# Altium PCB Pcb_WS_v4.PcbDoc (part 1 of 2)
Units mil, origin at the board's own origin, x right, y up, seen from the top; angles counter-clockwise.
Board outline 3890 x 3890 mil, 2 copper layers (Top Layer, Bottom Layer), stack 50.044 mil thick; 84 components, 65 nets, 260 pads, 445 vias.
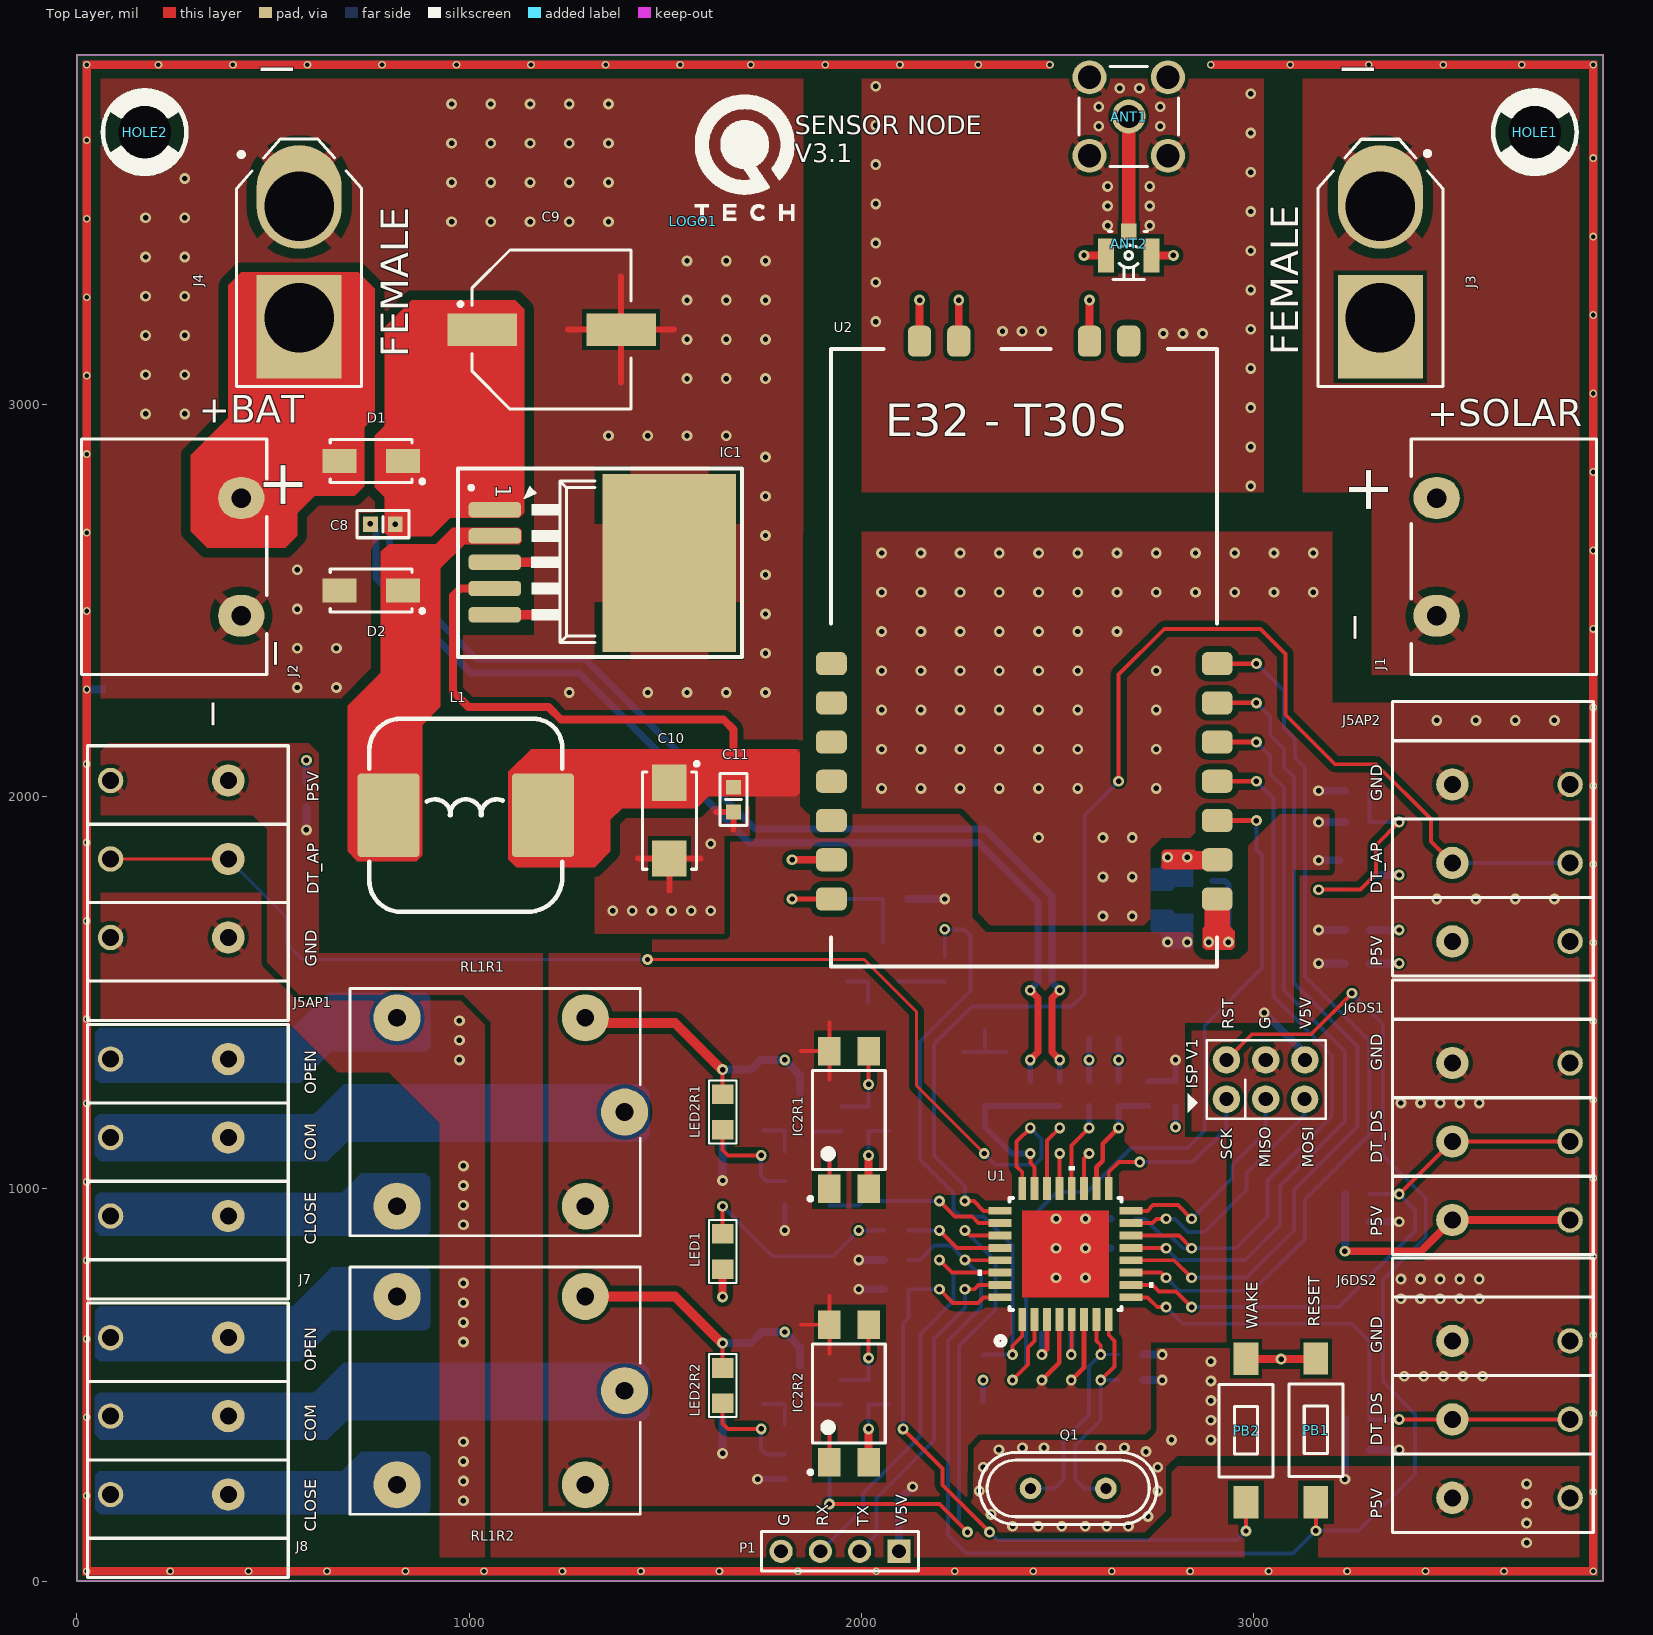
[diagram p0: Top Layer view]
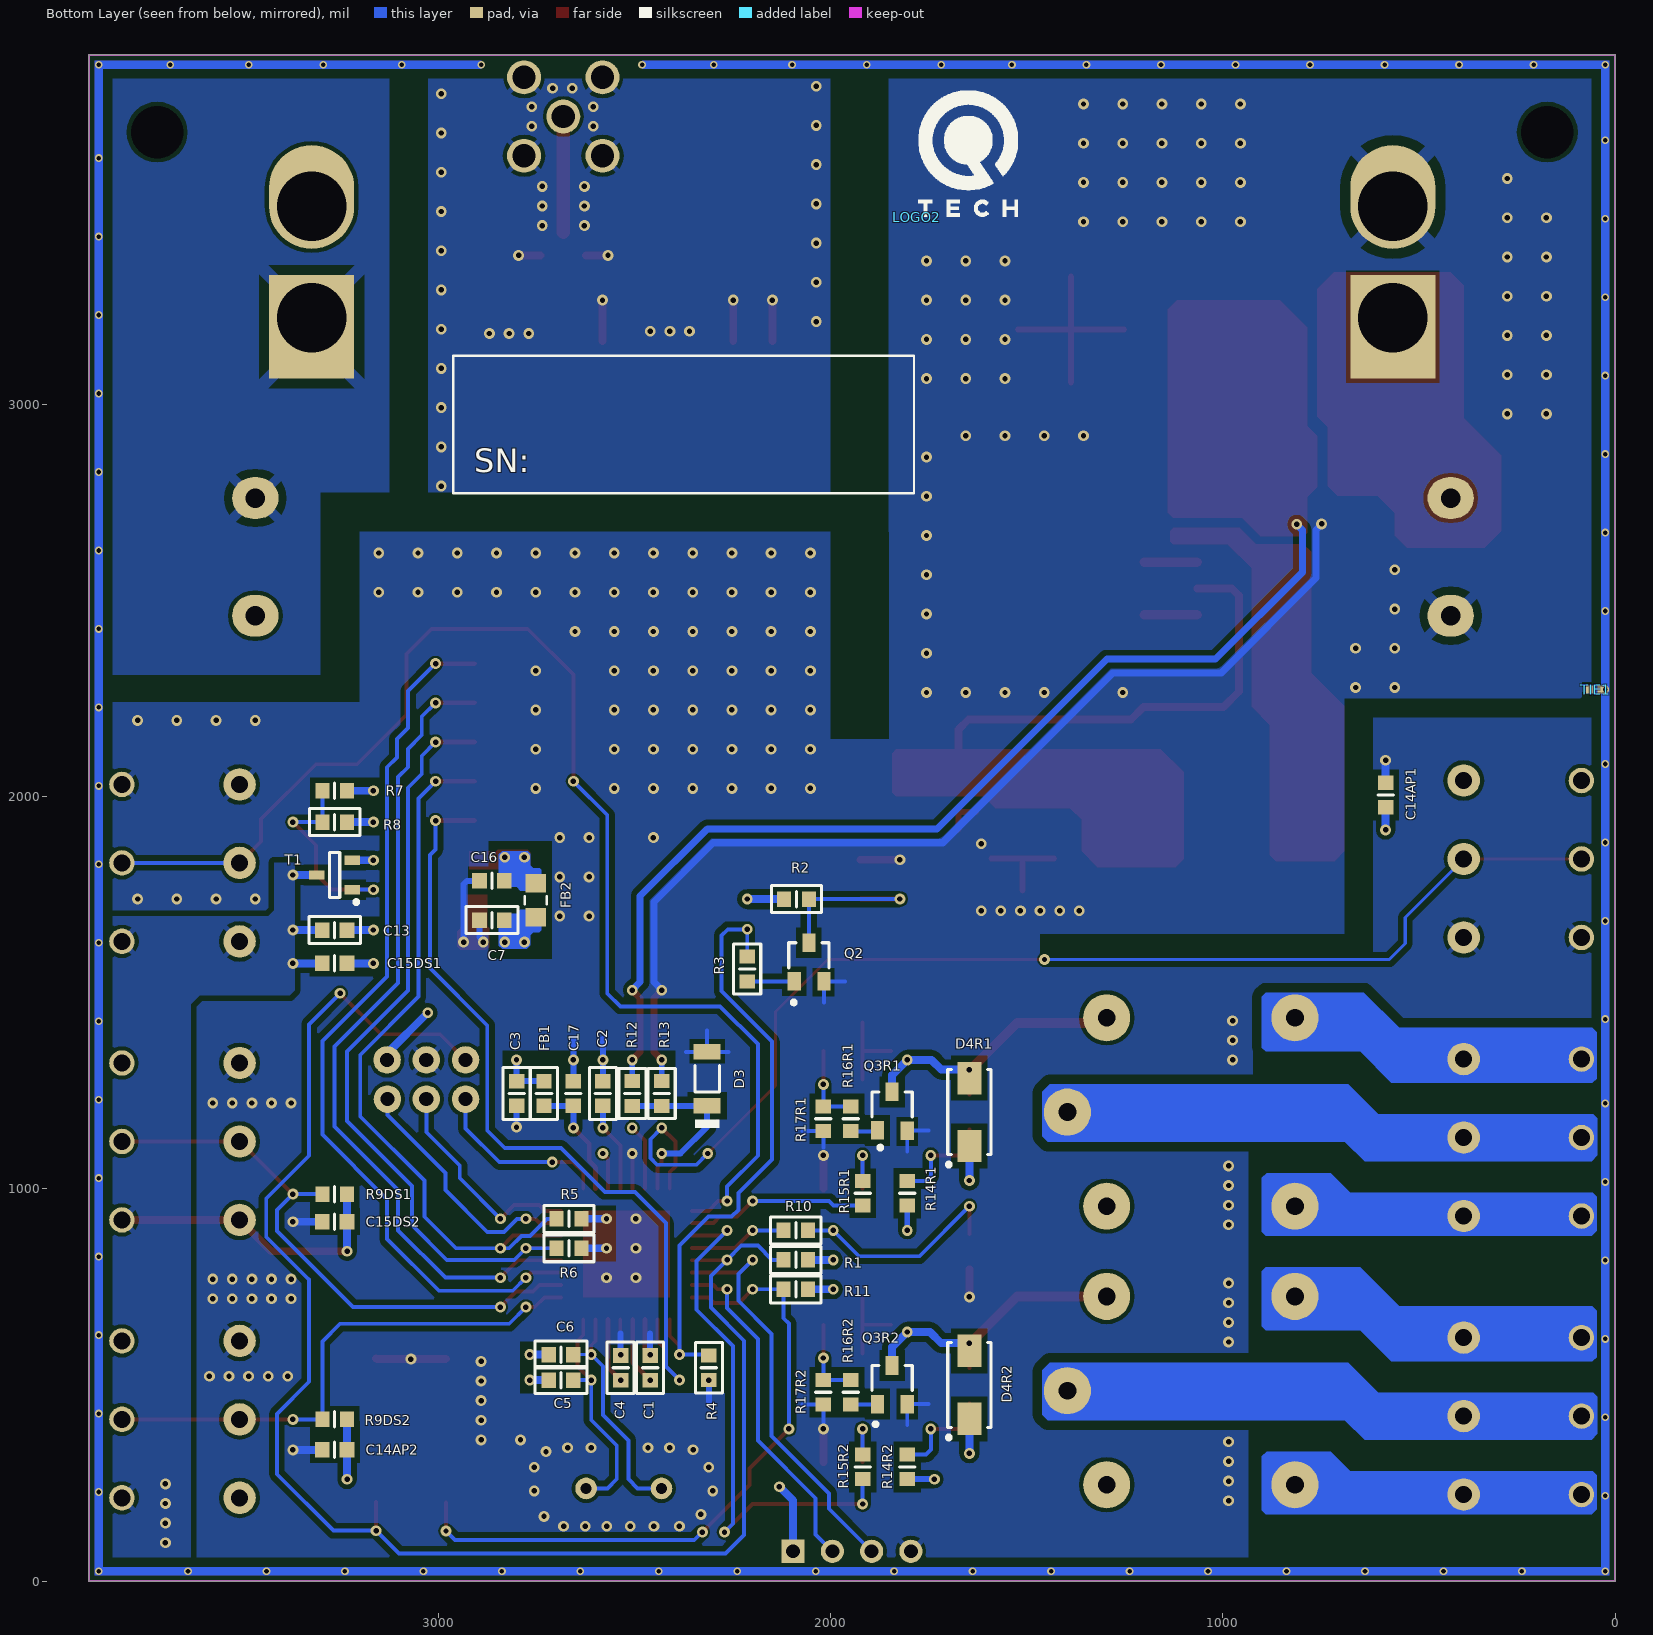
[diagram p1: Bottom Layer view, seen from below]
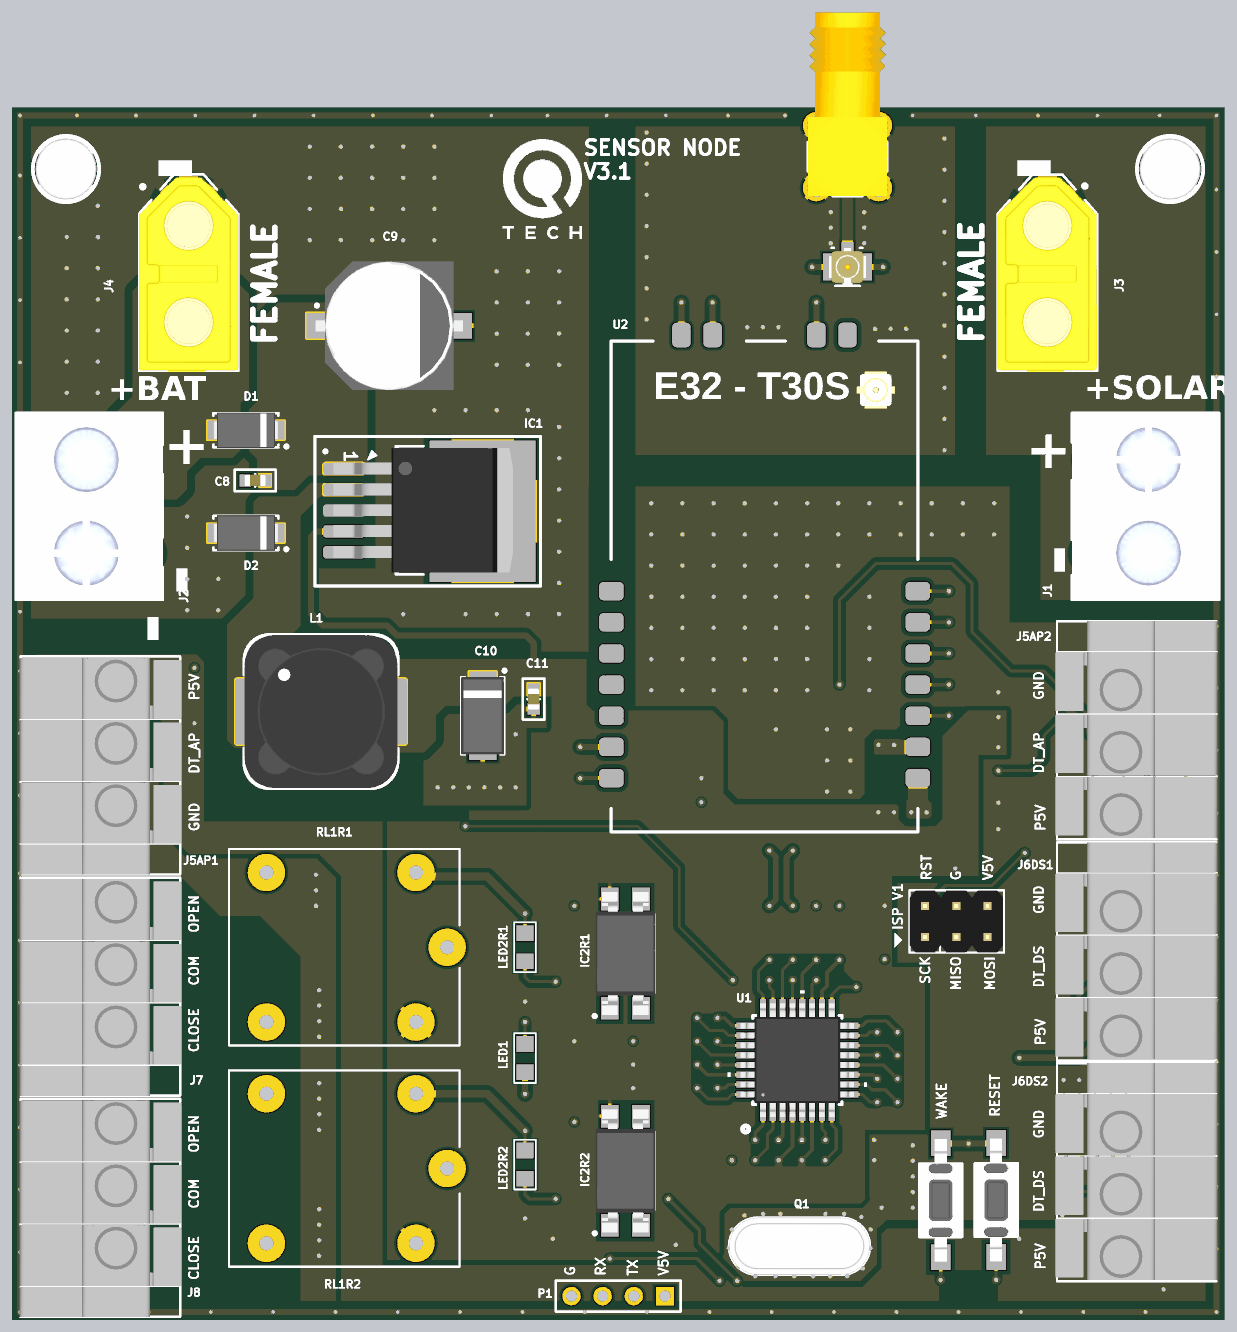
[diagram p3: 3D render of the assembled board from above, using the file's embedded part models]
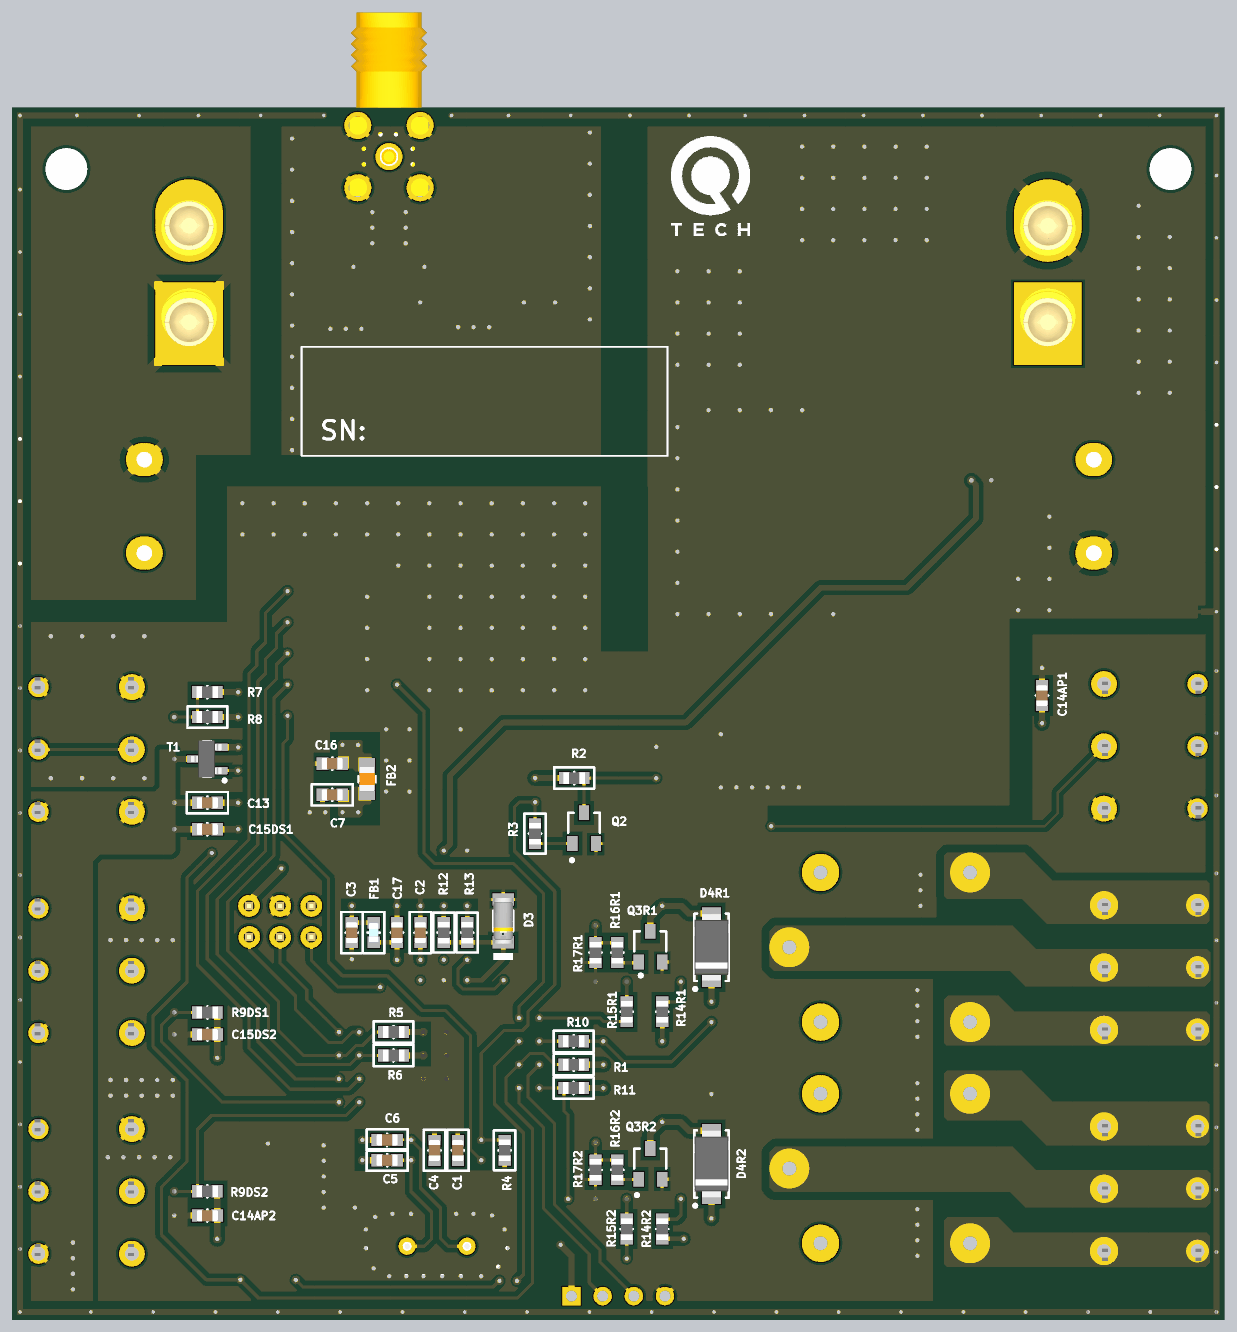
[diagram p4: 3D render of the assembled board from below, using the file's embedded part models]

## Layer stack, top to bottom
Top Solder: solder mask 0.4, Solder Resist, Dk 3.5
Top Layer: signal copper 1.4
Dielectric 1: dielectric 47.2441, FR-4, Dk 4.8
Bottom Layer: signal copper 1.4
Bottom Solder: solder mask 0.4, Solder Resist, Dk 3.5

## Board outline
0,0 0,3890 3890,3890 3890,0

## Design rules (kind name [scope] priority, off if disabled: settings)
Clearance ANT [InNet('ANT_M1') vs InNet('GND_ANT')] p1: gap=7.87 ignorepadtopadclearanceinfootprint=FALSE
Clearance Keep_Out [OnLayer('Keep-Out Layer')] p2: gap=5 ignorepadtopadclearanceinfootprint=FALSE
Clearance [All] p3: gap=10 ignorepadtopadclearanceinfootprint=FALSE except(5: Via-Poly Via-Region; 15: Track-Poly Track-Region SMDPad-Poly SMDPad-Region Poly-Poly; 25: Poly-Region)
ComponentClearance KF-conn_Clearance [InComponentClass('KF_conn') vs InComponentClass('KF_conn')] p1: gap=5 collisioncheckmode=3 verticalgap=0 showdistances=FALSE
ComponentClearance HS_Comp_Clearance [InComponentClass('HS_Comp') vs IsComponent] p2: gap=165 collisioncheckmode=3 verticalgap=0 showdistances=FALSE
ComponentClearance IC_Comp_Clearance [InComponentClass('IC_Comp') vs IsComponent] p3: gap=150 collisioncheckmode=3 verticalgap=0 showdistances=FALSE
ComponentClearance conn-th_Clearance [InComponentClass('conn-th') vs IsComponent and not InComponentClass('conn-th')] p4: gap=150 collisioncheckmode=3 verticalgap=0 showdistances=FALSE
ComponentClearance chip-ge_Clearance [InComponentClass('chip-ge') vs InAnyComponent] p5: gap=75 collisioncheckmode=3 verticalgap=0 showdistances=FALSE
ComponentClearance chip-0603_Clearance [InComponentClass('chip-0603') vs IsComponent] p6: gap=25 collisioncheckmode=3 verticalgap=0 showdistances=FALSE
HoleSize [All] p1: absolutevalues=TRUE maxlimit=100 minlimit=11.81 maxpercent=80.000 minpercent=20.000
HoleToHoleClearance [All] p1: gap=20 allowstackedmicrovias=TRUE
MinimumSolderMaskSliver MinimumForIC [HasFootprint('32A_ATM-M') vs HasFootprint('32A_ATM-M')] p1: minsoldermaskwidth=3
MinimumSolderMaskSliver [All] p2: minsoldermaskwidth=5
NetAntennae [All] p1 off: netantennaetolerance=0
PolygonConnect [All] p1: thpad.connectstyle=Relief thpad.reliefconductorwidth=13.78 thpad.reliefentries=4 thpad.polygonreliefangle="45 Angle" thpad.airgapwidth=10 smdpad.connectstyle=NoConnect smdpad.reliefconductorwidth=11.81 smdpad.reliefentries=4 smdpad.polygonreliefangle="45 Angle" smdpad.airgapwidth=10 via.connectstyle=Direct via.reliefconductorwidth=10 via.reliefentries=4 via.polygonreliefangle="90 Angle" via.airgapwidth=10
RoomDefinition Top_Level [InComponentClass('Top_Level')] p1: confinementstyle=ConfineIn formatcopy=TRUE lockcomponents=FALSE outline -1409.14,-1234.46 590.86,-1234.46 590.86,-234.46 -1409.14,-234.46
RoomDefinition R2 [InComponentClass('R2')] p2: confinementstyle=ConfineIn formatcopy=TRUE lockcomponents=FALSE outline -1409.14,-1234.46 590.86,-1234.46 590.86,-234.46 -1409.14,-234.46
RoomDefinition R1 [InComponentClass('R1')] p3: confinementstyle=ConfineIn formatcopy=TRUE lockcomponents=FALSE outline -1409.14,-1234.46 590.86,-1234.46 590.86,-234.46 -1409.14,-234.46
RoomDefinition PWR [InComponentClass('PWR')] p4: confinementstyle=ConfineIn formatcopy=TRUE lockcomponents=FALSE outline -1409.14,-1234.46 590.86,-1234.46 590.86,-234.46 -1409.14,-234.46
RoomDefinition Main [InComponentClass('Main')] p5: confinementstyle=ConfineIn formatcopy=TRUE lockcomponents=FALSE outline -1409.14,-1234.46 590.86,-1234.46 590.86,-234.46 -1409.14,-234.46
RoomDefinition Lora [InComponentClass('Lora')] p6: confinementstyle=ConfineIn formatcopy=TRUE lockcomponents=FALSE outline -1409.14,-1234.46 590.86,-1234.46 590.86,-234.46 -1409.14,-234.46
RoomDefinition Hardware [InComponentClass('Hardware')] p7: confinementstyle=ConfineIn formatcopy=TRUE lockcomponents=FALSE outline -1409.14,-1234.46 590.86,-1234.46 590.86,-234.46 -1409.14,-234.46
RoomDefinition DS2 [InComponentClass('DS2')] p8: confinementstyle=ConfineIn formatcopy=TRUE lockcomponents=FALSE outline -1409.14,-1234.46 590.86,-1234.46 590.86,-234.46 -1409.14,-234.46
RoomDefinition DS1 [InComponentClass('DS1')] p9: confinementstyle=ConfineIn formatcopy=TRUE lockcomponents=FALSE outline -1409.14,-1234.46 590.86,-1234.46 590.86,-234.46 -1409.14,-234.46
RoomDefinition AP2 [InComponentClass('AP2')] p10: confinementstyle=ConfineIn formatcopy=TRUE lockcomponents=FALSE outline -1409.14,-1234.46 590.86,-1234.46 590.86,-234.46 -1409.14,-234.46
RoomDefinition AP1 [InComponentClass('AP1')] p11: confinementstyle=ConfineIn formatcopy=TRUE lockcomponents=FALSE outline -1409.14,-1234.46 590.86,-1234.46 590.86,-234.46 -1409.14,-234.46
RoutingVias [All] p1: holewidth=13.78 width=27.56 viastyle="Through Hole" minholewidth=11.81 minwidth=23.62 maxholewidth=19.68 maxwidth=39.37
SilkToSilkClearance [All] p1: silktosilkclearance=3
SilkToSolderMaskClearance [IsPad] p1: minsilkscreentomaskgap=5 clearancetoexposedcopper=TRUE
SolderMaskExpansion [All] p1: expansion=4 istentingtop=FALSE
Width [All] p1: maxlimit=196.85 minlimit=8 preferedwidth=10
23 further rules are at their usual default settings.

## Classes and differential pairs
component class Hardware: HOLE1 HOLE2 LOGO1 LOGO2
channel class Sensor_DS18b20_1Wire: DS1 DS2
channel class Sensor_AirPressure_1Wire: AP1 AP2
channel class Relay: R1 R2
component class Top_Level: D3 J7 J8 LED1 P1 PB2 R10 R11 R12 R13 TIE1
component class R2: D4R2 IC2R2 LED2R2 Q3R2 R14R2 R15R2 R16R2 R17R2 RL1R2
component class R1: D4R1 IC2R1 LED2R1 Q3R1 R14R1 R15R1 R16R1 R17R1 RL1R1
component class Main: C1 C2 C3 C4 C5 C6 C17 FB1 "ISP V1" PB1 Q1 R1 U1
component class Lora: ANT1 ANT2 C7 C16 FB2 Q2 R2 R3 R4 R5 R6 U2
component class DS2: C15DS2 J6DS2 R9DS2
component class DS1: C15DS1 J6DS1 R9DS1
component class AP2: C14AP2 J5AP2
component class AP1: C14AP1 J5AP1
component class PWR: C8 C9 C10 C11 C13 D1 D2 IC1 J1 J2 J3 J4 L1 R7 R8 T1

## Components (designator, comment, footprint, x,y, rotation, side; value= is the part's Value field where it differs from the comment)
ANT1 "Coax_1Female_1Shield" "HUBER-SUHNER_85 SMA-50-0-101/111 NE" 2680.84,3733 r90 top
ANT2 "U.FL" HIROSE_U.FL-R-SMT-1(10) 2680.84,3379 r180 top
C1 "100nF" CAPC1608X87N 2459.61,543.68 r90 bottom
C2 "100nF" CAPC1608X87N 2580,1242.82 r270 bottom
C3 "100nF" CAPC1608X87N 2800,1242.82 r270 bottom
C4 "100nF" CAPC1608X87N 2534.61,543.68 r90 bottom
C5 "100nF" CAPC1608X87N 2686.8,512.18 r0 bottom value=22pF
C6 "100nF" CAPC1608X87N 2686.8,577.18 r0 bottom value=22pF
C7 "100nF" CAPC1608X87N 2862.78,1684.95 r180 bottom
C8 "100nF" CAPC1608X87N 780,2693.89 r180 top
C9 "470uF" CAPAE1030X1020N 1210,3190 r0 top
C10 "100uF" CAPMP6032X280N 1510,1938.49 r270 top
C11 "100nF" CAPC1608X87N 1673.55,1992 r270 top
C13 "100nF" CAPC1608X87N 3263.5,1659.46 r180 bottom
C14AP1 "100nF" CAPC1608X87N 585,2003.5 r270 bottom (schematic designator C14)
C14AP2 "100nF" CAPC1608X87N 3263.5,334.46 r180 bottom (schematic designator C14)
C15DS1 "100nF" CAPC1608X87N 3263.5,1574.46 r0 bottom (schematic designator C15)
C15DS2 "100nF" CAPC1608X87N 3263.5,915.77 r180 bottom (schematic designator C15)
C16 "2.2uF" CAPC1608X87N 2862.78,1784.92 r180 bottom
C17 "2.2uF" CAPC1608X87N 2655,1242.82 r270 bottom
D1 "SS16" DIOM5127X229N 750,2855 r180 top
D2 "SS16" DIOM5127X229N 750,2525 r180 top
D3 "BZV55-B5V1" DIOMELF3515N 2314.07,1280.22 r90 bottom
D4R1 "BZG03C220" DIOM5326X230N 1645.86,1195.54 r90 bottom (schematic designator D4)
D4R2 "BZG03C220" DIOM5326X230N 1645.86,500 r90 bottom (schematic designator D4)
FB1 "Ferrite bead Case 0603" Chip_0603 2730,1242.82 r90 bottom
FB2 "Ferrite bead Case 0805" CHIP_0805 2751.03,1735.52 r90 bottom
HOLE1 "HOLE" "HOLE M3" 3716.02,3693.14 r0 top
HOLE2 "HOLE" "HOLE M3" 172.71,3693.14 r0 top
IC1 "LM2596" TO263-5 1065.04,2730.82 r270 top
IC2R1 "SFH6156-4" SOIC254P977X406-4N 1967.86,1175.54 r90 top (schematic designator IC2)
IC2R2 "SFH6156-4" SOIC254P977X406-4N 1967.86,478.26 r90 top (schematic designator IC2)
"ISP V1" "Connector 3x2" JP3x2 3030,1278.39 r0 top
J1 "CON KF7.62-2P" "CON KF7.62-2P" 3465.86,2610.54 r270 top locked
J2 "CON KF7.62-2P" "CON KF7.62-2P" 418.93,2610.54 r90 top locked
J3 "XT60-FM" XT60-FM 3322.31,3362.43 r270 top locked
J4 "XT60-FM" XT60-FM 566.41,3362.43 r270 top locked
J5AP1 "KF142V-3P" "CON KF142V-3P-5.08" 85.86,2040.54 r270 top (schematic designator J5)
J5AP2 "KF142V-3P" "CON KF142V-3P-5.08" 3805.86,1630.54 r90 top (schematic designator J5)
J6DS1 "KF142V-3P" "CON KF142V-3P-5.08" 3805.86,920.54 r90 top (schematic designator J6)
J6DS2 "KF142V-3P" "CON KF142V-3P-5.08" 3805.86,212.26 r90 top (schematic designator J6)
J7 "KF142V-3P" "CON KF142V-3P-5.08" 85.86,1330.54 r270 top
J8 "KF142V-3P" "CON KF142V-3P-5.08" 85.86,620.54 r270 top
L1 "33uH" L_SMD 794.25,1952 r90 top
LED1 "LED" L-0805 1645.86,840 r270 top value="LED 3 ly Single Colour"
LED2R1 "LED" L-0805 1645.86,1195.54 r90 top value="LED 3 ly Single Colour" (schematic designator LED2)
LED2R2 "LED" L-0805 1645.86,498.26 r90 top value="LED 3 ly Single Colour" (schematic designator LED2)
LOGO1 "LOGO" LOGO-QTECH 1570.5,3466.4 r0 top
LOGO2 "LOGO" LOGO-QTECH 1780,3476 r180 bottom
P1 "Header 4" HDR1X4 2095,76 r180 top
PB1 "Push Button" PB_TYCO_FSMSM 3157.89,384.26 r90 top
PB2 "Push Button" PB_TYCO_FSMSM 2979.87,383.49 r90 top
Q1 "20MHz" XTAL_HC-49/U 2526.55,236.12 r0 top
Q2 "C1815" SOT23-3 2055.2,1577.8 r180 bottom
Q3R1 "C1815" SOT23-3 1842.86,1197.59 r180 bottom (schematic designator Q3)
Q3R2 "C1815" SOT23-3 1842.86,500.31 r180 bottom (schematic designator Q3)
R1 "10k" RESC1608X55N 2088.21,818.79 r0 bottom
R2 "10k" RESC1608X55N 2086.5,1738.49 r0 bottom value=4k7
R3 "10k" RESC1608X55N 2212.06,1560.29 r270 bottom value=1k
R4 "10k" RESC1608X55N 2309.61,543.68 r90 bottom value=1k
R5 "4k7" RESC1608X55N 2666.17,923.39 r180 bottom value=10k
R6 "4k7" RESC1608X55N 2666.17,848.39 r180 bottom value=10k
R7 "1k" RESC1608X55N 3263.5,2014.46 r0 bottom
R8 "10k" RESC1608X55N 3263.5,1934.46 r0 bottom
R9DS1 "4k7" RESC1608X55N 3263.5,986.31 r180 bottom (schematic designator R9)
R9DS2 "4k7" RESC1608X55N 3263.5,412.26 r180 bottom (schematic designator R9)
R10 "10k" RESC1608X55N 2088.21,893.79 r180 bottom value=200
R11 "10k" RESC1608X55N 2088.21,743.79 r0 bottom
R12 "10k" RESC1608X55N 2505,1242.82 r270 bottom value=2M
R13 "10k" RESC1608X55N 2430,1242.82 r90 bottom value=1M
R14R1 "1k" RESC1608X55N 1804.06,988.52 r90 bottom value=200 (schematic designator R14)
R14R2 "1k" RESC1608X55N 1804.06,291.24 r90 bottom value=200 (schematic designator R14)
R15R1 "1k" RESC1608X55N 1917.86,988.52 r90 bottom (schematic designator R15)
R15R2 "1k" RESC1608X55N 1917.86,291.24 r90 bottom (schematic designator R15)
R16R1 "1k" RESC1608X55N 1947.86,1178.52 r270 bottom value=200 (schematic designator R16)
R16R2 "1k" RESC1608X55N 1947.86,481.24 r270 bottom value=200 (schematic designator R16)
R17R1 "10k" RESC1608X55N 2017.86,1178.52 r90 bottom (schematic designator R17)
R17R2 "10k" RESC1608X55N 2017.86,481.24 r90 bottom (schematic designator R17)
RL1R1 "Relay 10A/12V" RL_SPDT_10A 1395.86,1195.54 r180 top value="Relay SPDT, 10A, 12V" (schematic designator RL1)
RL1R2 "Relay 10A/12V" RL_SPDT_10A 1395.86,485.54 r180 top value="Relay SPDT, 10A, 12V" (schematic designator RL1)
T1 "BSH203" SOT95P230X110-3N 3263.5,1799.74 r0 bottom
TIE1 "TIE" tie 49.76,2272.5 r0 bottom
U1 "ATmega328-AU" 32A_ATM-M 2519.8,833.59 r90 top
U2 "E32-T30S" E32-T30S 2906.43,3140.85 r180 top locked

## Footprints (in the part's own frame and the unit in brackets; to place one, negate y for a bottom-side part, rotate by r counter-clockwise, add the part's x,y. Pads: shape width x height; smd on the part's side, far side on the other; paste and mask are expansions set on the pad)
32A_ATM-M [mil]
  rect 58x20 smd: 1(-167,110.24) 2(-167,78.74) 3(-167,47.24) 4(-167,15.75) 5(-167,-15.75) 6(-167,-47.24) 7(-167,-78.74) 8(-167,-110.24) 17(167,-110.24) 18(167,-78.74) 19(167,-47.24) 20(167,-15.75) 21(167,15.75) 22(167,47.24) 23(167,78.74) 24(167,110.24)
  rect 20x58 smd: 9(-110.24,-167) 10(-78.74,-167) 11(-47.24,-167) 12(-15.75,-167) 13(15.75,-167) 14(47.24,-167) 15(78.74,-167) 16(110.24,-167) 25(110.24,167) 26(78.74,167) 27(47.24,167) 28(15.75,167) 29(-15.75,167) 30(-47.24,167) 31(-78.74,167) 32(-110.24,167)
  silkscreen extent -231,-224 224,224, body extent -182,-182 182,182, height 47
CAPAE1030X1020N [mm] "Capacitor, Aluminium Electrolytric, 10.3mm L X 10.3mm W X 10.2mm H, IPC Medium Density"
  rect 4.5x2.1 smd: 1(-4.5,0) 2(4.5,0)
  silkscreen extent -6.02,-5.15 5.15,5.15, body extent -6,-5.25 6,5.25, height 10.2
CAPC1608X87N [mm] "Chip Capacitor, Body 1.6x0.8mm IPC Medium Density"
  rect 0.95x1 smd: 1(-0.8,0) 2(0.8,0)
  silkscreen extent -1.68,-0.87 1.68,0.87, body extent -0.87,-0.47 0.88,0.48, height 0.87
CAPMP6032X280N [mm] "Capacitor, Polarized, Molded  Body 6.0x3.2mm, IPC Medium Density"
  rect 2.35x2.25 smd: 1(-2.45,0) 2(2.45,0)
  silkscreen extent -3.8,-1.75 3.15,1.9, body extent -3.15,-1.75 3.15,1.75, height 2.8
Chip_0603 [mm]
  rect 0.95x1 smd: 1(0.8,0) 2(-0.8,0)
  silkscreen extent -1.68,-0.87 1.68,0.87, body extent -0.8,-0.4 0.8,0.4, height 0.95
CHIP_0805 [mm]
  rect 1.2x1.3 smd mask+0.064: 1(-1.1,0) 2(1.1,0)
  silkscreen extent -0.28,-0.71 0.25,0.71, body extent -1,-0.62 1,0.63, height 0.88
"CON KF7.62-2P" [mm]
  oval 2.7x3 hole 1.26: 1(-3.81,0) 2(3.81,0)
  silkscreen extent -7.62,-1.65 7.62,10.35, body extent -7.62,-1.65 7.62,10.35, height 12.4
"CON KF142V-3P-5.08" [mm]
  round 2.1 hole 1.1: 1(0,7.62) 2(5.08,7.62) 3(10.16,7.62)
  round 1.65 hole 1.1: 1(0,0) 2(5.08,0) 3(10.16,0)
  silkscreen extent -2.25,-1.5 15.53,11.5, body extent -2.14,-1.57 15.54,11.63, height 14.23
DIOM5127X229N [mm] "DO-214-AC/SMA Molded Diode, 2-Leads, Body 5.1x2.7mm, IPC Medium Density"
  rect 2.2x1.55 smd: 1(-2.05,0) 2(2.05,0)
  silkscreen extent -3.43,-1.4 2.65,1.45, body extent -2.67,-1.45 2.68,1.45, height 2.29
DIOM5326X230N [mm] "DO-214-AC/SMA Molded Diode, Body 5.3x2.6mm, IPC Medium Density"
  rect 2.1x1.55 smd: 1(-2.2,0) 2(2.2,0)
  silkscreen extent -3.52,-1.4 2.75,1.45, body extent -2.75,-1.4 2.75,1.4, height 2.3
DIOMELF3515N [mm] "SOD80C, MELF Diode, 2-Leads, Body 3.5x1.5mm, IPC Medium Density"
  rect 1x1.75 smd: 1(-1.75,0) 2(1.75,0)
  silkscreen extent -3.18,-0.8 0.85,0.8, body extent -1.85,-0.8 1.85,0.8, height 1.6
E32-T30S [mm] "Lora-EBYTE-21~30dBm-UART-SX1278-25x40mm"
  rrect50% 2x1.5 smd: 1(0,20.38) 2(0,22.92) 3(0,25.46) 4(0,28) 5(0,30.54) 6(0,33.08) 7(0,35.62) 8(24.98,35.62) 9(24.98,33.08) 10(24.98,30.54) 11(24.98,28) 12(24.98,25.46) 13(24.98,22.92) 14(24.98,20.38)
  rrect50% 1.5x2 smd: 15(19.27,-0.5) 16(16.73,-0.5) 17(8.27,-0.5) 18(5.73,-0.5)
  silkscreen extent 0,0 25,40, body extent 0,0 25,40, height 3.5
HDR1X4 [mm] "Connector; Header; 4 Position"
  rect 1.5x1.5 hole 0.9: 1(0,0)
  round 1.5 hole 0.9: 2(2.54,0) 3(5.08,0) 4(7.62,0)
  silkscreen extent -1.27,-1.27 8.89,1.27
HIROSE_U.FL-R-SMT-1(10) [mm] "Up to 6GHz Ultra Small Surface Mount Male Coaxial Connectors U.FL Series"
  rect 1x1.05 smd: 1(0,-1.525)
  rect 1.05x2.2 smd: 2(-1.475,0) 2(1.475,0)
  silkscreen extent -1.21,-1.55 1.3,1.55, body extent -1.5,-1.55 1.5,1.55, height 1.25
"HOLE M3" [mm]
  round 3.2 hole 3.4 unplated mask+0.1: 1(0,0)
  Top Layer pour cut-out: -2.846,0.006 -2.628,1.101 -2.007,2.029 -1.077,2.646 0.019,2.859 0.019,2.859 1.117,2.635 2.042,2.003 2.649,1.062 2.845,-0.041 2.845,-0.041 2.628,-1.12 2.013,-2.033 1.094,-2.64 0.012,-2.845 0.012,-2.845 -1.086,-2.638 -2.017,-2.021 -2.636,-1.091 -2.846,0.006
  silkscreen extent -2.7,-2.7 2.7,2.7, body extent -2.5,-2.5 2.5,2.5, height 1.73
"HUBER-SUHNER_85 SMA-50-0-101/111 NE" [mm] "50 Ohm SMA Right Angle PCB Jack"
  round 2.2 hole 1.5: 1(0,0) 2(-2.54,-2.54) 2(-2.54,2.54) 2(2.54,-2.54) 2(2.54,2.54)
  silkscreen extent -3.23,-3.23 3.23,3.23, body extent -3.23,-3.23 11.73,3.23, height 9.6
JP3x2 [mil] "Connector 3x2"
  round 70 hole 36: 1(-100,-50) 2(0,-50) 3(99,-50) 4(-100,50) 5(0,50) 6(100,50)
  silkscreen extent -199,-100 153,100, body extent -150,-100 150,100, height 335
L-0805 [mil] "Compoment SMD 80x50mil"
  rect 50x55 smd: 1(-45,0) 2(45,0)
  silkscreen extent -80,-35 80,35, body extent -50,-20 50,20, height 43
L_SMD [mm]
  rrect10% 5.4x4 smd mask+0.1: 1(0,0) 2(0,-10)
  silkscreen extent -6.25,-11.25 6.25,1.25, body extent -6.25,-11.25 6.25,1.25, height 6.7
LOGO-QTECH [mil]
  silkscreen extent 4,2 258,322
PB_TYCO_FSMSM [mm] "Body 3.5x6.0mm, Pushbutton Switch,  TYCO FSMSM Serie"
  rect 2.1x1.6 smd: 1(-4.65,0) 2(4.65,0)
  silkscreen extent -3,-1.75 3,1.75, body extent -5,-1.75 5,1.75, height 4.3
RESC1608X55N [mm] "Chip Resistor, EIA 0603, Metric 1608, Body 1.6x0.8mm, IPC Medium Density"
  rect 0.9x1 smd: 1(-0.8,0) 2(0.8,0)
  silkscreen extent -1.63,-0.87 1.63,0.87, body extent -0.87,-0.47 0.88,0.48, height 0.55
RL_SPDT_10A [mil] "Relay SPDT, 5 pin, 10A,W 650mil, L 800mil, H 800mil"
  round 120 hole 45: 1(0,0) 2(580,240) 3(580,-240) 4(100,-240) 5(100,240)
  silkscreen extent -40,-315 700,315
SOIC254P977X406-4N [mm] "SOIC, 2.54mm pitch; 4 pin, 6.65mm W X 4.69mm L, IPC Medium Density"
  rect 1.85x1.45 smd: 1(-4.45,1.27) 2(-4.45,-1.27) 3(4.45,-1.27) 4(4.45,1.27)
  silkscreen extent -5.22,-2.35 3.2,2.62, body extent -5.01,-2.41 5.02,2.42, height 4.06
SOT23-3 [mm] "SOT 23"
  rect 0.85x1.2 smd: 1(-0.94,-1.245) 2(0.985,-1.25) 3(0.005,1.25)
  silkscreen extent -1.29,-2.74 1.31,1.25, body extent -1.5,-1.5 1.52,1.5, height 1.27
SOT95P230X110-3N [mm] "SOT23, 3 pin, Pitch 0.95mm - 1.3mm W X 2.9mm L X 1.1mm H, IPC Medium Density"
  rect 1x0.6 smd: 1(-1.15,0.95) 2(-1.15,-0.95) 3(1.15,0)
  silkscreen extent -1.52,-1.45 0.33,1.87, body extent -1.17,-1.5 1.33,1.5, height 1.1
tie [mm]
  rect 0.5x0.5 smd paste-1 mask+0.102: 1(0.375,0) 2(-0.375,0)
  Top Layer region: -0.625,0.25 0.625,0.25 0.625,-0.25 -0.625,-0.25
TO263-5 [mm]
  rrect50% 1x3.4 smd: 1(0,0) 2(1.7,0) 4(5.1,0) 5(6.8,0)
  rrect50% 1x3.4 smd mask+0: 3(3.4,0)
  rect 11.5x8.634 smd: 6(3.45,11.302)
  silkscreen extent -2.66,-2.38 9.54,16.02, body extent -1.71,-0.87 8.45,13.77, height 4.57
XT60-FM [mm]
  oval 6.716x5.516 hole 4.5 copper offset -0.6,0: 1(-3.6,0)
  rect 6.716x5.516 hole 4.5 copper offset 0.6,0: 2(3.6,0)
  silkscreen extent -7.94,-4.05 8.06,4.05, body extent -7.81,-4.07 8.12,4.06, height 15.5
XTAL_HC-49/U [mm] "HC-49/U Leaded Cristal, Body 11.05x4.8mm; Pitch 4.88mm"
  round 1.4 hole 0.7: 1(-2.44,0) 2(2.44,0)
  silkscreen extent -5.75,-2.33 5.75,2.33, body extent -5.75,-2.33 5.75,2.33, height 3.5

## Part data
ANT1: library part HUBER-SUHNER_85_SMA-50-0-101/111_NE, Manufacturer=HUBER+SUHNER, Manufacturer Part Number=85_SMA-50-0-101/111_NE
ANT2: library part HIROSE_U.FL-R-SMT-1(10), Manufacturer="HIROSE (HRS)", Manufacturer Part Number=U.FL-R-SMT-1(10)
C1 C2 C3 C4 C7 C8 C11 C13 C14AP1 C14AP2 C15DS1 C15DS2: library part CC0603_100NF_50V_10%_X7R, "Non-polarised capacitor", Case=0603, Manufacturer=GENERIC, Manufacturer1 ComponentHeight=0.87mm, Manufacturer1 Example=PHYCOMP, Manufacturer1 Part Number=223858615649, Tolerance=±10%, Voltage=50V
C5 C6: library part CC0603_22PF_50V_5%_NP0, "Non-polarised capacitor", Case=0603, Manufacturer=GENERIC, Manufacturer1 ComponentHeight=0.87mm, Manufacturer1 Example=PHYCOMP, Manufacturer1 Part Number=223886715229, Tolerance=±5%, Voltage=50V
C9: library part CAE1030-1020_470UF_25V_20%, "Polarised capacitor", Case=G, Manufacturer=GENERIC, Manufacturer1 ComponentHeight=10.2mm, Manufacturer1 Example=PANASONIC, Manufacturer1 Part Number=EEEFK1E471AP, Tolerance=±20%, Voltage=25V
C10: library part CTE6032-28_100UF_6.3V_10%_LESR0075, "Polarised capacitor", Case=C, Manufacturer=GENERIC, Manufacturer1 ComponentHeight=2.8mm, Manufacturer1 Example=AVX, Manufacturer1 Part Number=TPSC107K006R0075, Tolerance=±10%, Voltage=6.3V
C16 C17: library part CC0603_2.2UF_16V_10%_X5R, "Non-polarised capacitor", Case=0603, Manufacturer=GENERIC, Manufacturer1 ComponentHeight=0.9mm, Manufacturer1 Example=YAGEO, Manufacturer1 Part Number=CC0603KRX5R7BB225, Tolerance=±10%, Voltage=16V
D1 D2: "Schottky Diode", Case=DO-214AC, Manufacturer="VISHAY GENERAL SEMICONDUCTOR", Power=1A, Voltage=60V
D3: "Zener Diode", Case=SOD-80C, Manufacturer="NXP SEMICONDUCTORS", Power=500mW, Voltage=5V1
D4R1 D4R2: "Zener Diode", Case=DO-214AC, Manufacturer="VISHAY SEMICONDUCTOR", Power=1.25W, Voltage=220V
FB1: library part FERRITE_0603, Manufacturer Part Number=MMZ1608R601ATD25
FB2: library part FERRITE_0805, Manufacturer Part Number=FBMH2012HM121-T
HOLE1 HOLE2: library part "HOLE M3"
IC1: library part LM2596-5V
IC2R1 IC2R2: "Single Optocoupler", Case=SOIC4, Manufacturer="VISHAY SEMICONDUCTORS"
"ISP V1": library part JP3x2
J3 J4: Package="Package Analog Devices"
J5AP1 J5AP2 J6DS1 J6DS2 J7 J8: library part "CON KF142V-3P-5.08", "CON KF142V-3P-5.08"
L1: library part "L_SMD 33uH"
LED1 LED2R1 LED2R2: "LED Single colour Green and Red"
P1: "Header, 4-Pin"
PB1 PB2: "Push-Button Switch SPDT", Manufacturer="TYCO ELECTRONICS", Manufacturer Part Number="FSMSM or 1437566-3", Part Number=PB_TYCO_FSMSM
Q1: library part XTAL_20MHZ_AEL_HC-49/U, "Quartz Crystal", Manufacturer="AEL CRYSTALS", Manufacturer Part Number=X20M000000L010
Q2 Q3R1 Q3R2: library part 2SC1815, PSpiceTemplate="Q^@REFDES %c %b %e @MODEL"
R1 R5 R6 R8 R11 R17R1 R17R2: library part R0603_10K_1%_0.1W_100PPM, "Resistor - 1%", Case=0603, Manufacturer=GENERIC, Manufacturer1 ComponentHeight=0.55mm, Manufacturer1 Example="NIC COMPONENT", Manufacturer1 Part Number=NRC06F1002TRF, Power=0.1W, Tolerance=±1%
R2 R9DS1 R9DS2: library part R0603_4K7_1%_0.1W_100PPM, "Resistor - 1%", Case=0603, Manufacturer=GENERIC, Manufacturer1 ComponentHeight=0.55mm, Manufacturer1 Example="NIC COMPONENT", Manufacturer1 Part Number=NRC06F4701TRF, Power=0.1W, Tolerance=±1%
R3 R4 R7 R15R1 R15R2: library part R0603_1K_1%_0.1W_100PPM, "Resistor - 1%", Case=0603, Manufacturer=GENERIC, Manufacturer1 ComponentHeight=0.55mm, Manufacturer1 Example="NIC COMPONENT", Manufacturer1 Part Number=NRC06F1001TRF, Power=0.1W, Tolerance=±1%
R10 R14R1 R14R2 R16R1 R16R2: library part R0603_200R_1%_0.1W_100PPM, "Resistor - 1%", Case=0603, Manufacturer=GENERIC, Manufacturer1 ComponentHeight=0.55mm, Manufacturer1 Example="NIC COMPONENT", Manufacturer1 Part Number=NRC06F2000TRF, Power=0.1W, Tolerance=±1%
R12: library part R0603_2M_1%_0.1W_100PPM, "Resistor - 1%", Case=0603, Manufacturer=GENERIC, Manufacturer1 ComponentHeight=0.55mm, Manufacturer1 Example="NIC COMPONENT", Manufacturer1 Part Number=NRC06F2004TRF, Power=0.1W, Tolerance=±1%
R13: library part R0603_1M_1%_0.1W_100PPM, "Resistor - 1%", Case=0603, Manufacturer=GENERIC, Manufacturer1 ComponentHeight=0.55mm, Manufacturer1 Example="NIC COMPONENT", Manufacturer1 Part Number=NRC06F1004TRF, Power=0.1W, Tolerance=±1%
RL1R1 RL1R2: library part "Relay 1", "Relay SPDT,10A - 12VDC 5 Pin"
T1: "P-CHANNEL MOSFET WITH DIODE", Case=SOT23-3, Manufacturer="NXP SEMICONDUCTORS"
U1: "8-bit AVR Microcontroller, 32KB Flash, 1KB EEPROM, 2KB SRAM, 32-pin TQFP, Industrial Grade (-40°C to 85°C)", Supplier Part Number 1=ATMEGA328-AU-ND
U2: library part E32-433T30S, "Lora Ebyte E32-T30S Module"

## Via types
v1: diameter 27.56, hole 13.78, Top Layer to Bottom Layer, tented both sides, 369 vias
v2: diameter 20, hole 11.81, Top Layer to Bottom Layer, tented both sides, 76 vias

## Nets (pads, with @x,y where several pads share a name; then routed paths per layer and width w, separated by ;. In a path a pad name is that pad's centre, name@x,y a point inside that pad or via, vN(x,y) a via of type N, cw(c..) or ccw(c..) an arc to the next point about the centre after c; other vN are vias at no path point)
ANT_M: U2.18
ANT_M1: ANT1.1 ANT2.1 | length 294
  Top Layer w35.43: ANT2.1@2680.84,3439.04 ANT1.1@2680.84,3733
AREF: C2.2 U1.20 | length 229.1
  Top Layer w10: U1.20@2535.55,1000.59 2535.55,1110.55 v1(2580,1155)
  Bottom Layer w15: v1(2580,1155) C2.2@2580,1211.32
AUX: U1.2 U2.5 | length 2101.9
  Top Layer w10: v1(2384.61,512.18) 2424.61,552.18 2424.61,595.81 2441.06,612.26 U1.2@2441.06,666.59
  Top Layer w12: U2.5@2906.43,1938.49 v1(3006.43,1938.49)
  Bottom Layer w10: v1(2384.61,512.18) 2419,546.57 2419,912.7 2498.33,992.02 2574.43,992.02 2686.4,1104 2830,1104 2874.61,1148.61 2874.61,1416.42 3020.39,1562.2 3020.39,1850.93 3006.43,1864.9 v1(3006.43,1938.49)
BAT-VSEN: C8.1 C9.1 D1.1 IC1.1 R12.1 | length 2654.9
  Top Layer w18: v1(2505,1328.39) 2485,1348.39 2485,1377.69 2485,1486 v1(2505,1506)
  Bottom Layer w15: R12.1@2505,1274.31 v1(2505,1328.39)
  Bottom Layer w18: v1(811.5,2693.89) 811.5,2693.06 797,2678.57 797,2571.24 1018.24,2350 1295,2350 1728,1917 2313.83,1917 2485,1745.83 2485,1526.7 2505,1506.7 v1(2505,1506)
BAT-VSEN-Q: D3.1 R12.2 R13.1 U1.23 | length 482.1
  Top Layer w10: v1(2430,1090) 2430,1065.98 2441.06,1054.92 U1.23@2441.06,1000.59
  Bottom Layer w15: v1(2430,1090) 2382.4,1090 2314.07,1158.32 D3.1@2314.07,1211.32 R13.1@2430,1211.32 R12.2@2505,1211.32
CLOSE1: J7.3 RL1R1.2
CLOSE2: J8.3 RL1R2.2
COM1: J7.2 RL1R1.1
COM2: J8.2 RL1R2.1
DATA-AP1: J5AP1.2 U1.24 | length 3115.9
  Top Layer w8: J5AP1.2@85.86,1840.54 J5AP1.2@385.86,1840.54 ; v1(1454.34,1584.37) 2007.1,1584.37 2140,1451.48 2140,1262.85 v1(2312.85,1090)
  Top Layer w10: U1.24@2409.57,1000.59 2409.57,1042.43 2395,1057 2395,1120 v1(2430,1155)
  Bottom Layer w8: J5AP1.2@385.86,1840.54 535,1691.4 535,1625 575.63,1584.37 v1(1454.34,1584.37)
  Bottom Layer w10: v1(2312.85,1090) 2341.63,1061.22 2441.92,1061.22 2458.78,1078.08 2458.78,1126.22 v1(2430,1155)
DATA-AP2: J5AP2.2 U1.25 | length 3387.9
  Top Layer w10: v1(2263.39,968.79) 2286,968.79 2310.96,943.83 U1.25@2352.8,943.83 ; v1(2655,2038.49) 2655,2310.55 2771.45,2427 3016.45,2427 3080,2363.45 3080,2208.21 3206.21,2082 3311.19,2082 3451.23,1941.96 3451.23,1885.17 J5AP2.2@3505.86,1830.54
  Bottom Layer w10: v1(2263.39,968.79) 2263.39,1005.82 2185,1084.21 2185,1368.51 2281.49,1465 2535.56,1465 2568.75,1498.2 2568.75,1952.24 v1(2655,2038.49) ; J5AP2.2@3505.86,1830.54 J5AP2.2@3805.86,1830.54
DATA-DS1: J6DS1.2 R9DS1.1 U1.10 | length 1504.9
  Top Layer w10: U1.10@2686.8,754.85 2741.13,754.85 2757.59,738.39 2801.21,738.39 v1(2841.21,698.39) ; v1(3370,986.31) 3370.82,986.31 3505.04,1120.54 J6DS1.2@3505.86,1120.54 J6DS1.2@3805.86,1120.54
  Bottom Layer w10: v1(2841.21,698.39) 3216.86,698.39 3410.58,892.11 3410.58,945.73 v1(3370,986.31) R9DS1.1@3295,986.31
DATA-DS2: J6DS2.2 R9DS2.1 U1.9 | length 1364.1
  Top Layer w10: U1.9@2686.8,723.35 2728.65,723.35 2753.61,698.39 v1(2776.21,698.39) ; v1(3370,412.26) J6DS2.2@3505.86,412.26 J6DS2.2@3805.86,412.26
  Bottom Layer w10: v1(2776.21,698.39) 2818.61,656 3249.65,656 3295,610.65 R9DS2.1@3295,412.26 v1(3370,412.26)
EARTH: TIE1.2
  other v2: 25,25 237.5,25 437.5,25 637.5,25 837.5,25 1037.5,25 1237.5,25 1437.5,25 1637.5,25 1837.5,25 2037.5,25 2237.5,25 2437.5,25 2637.5,25 2837.5,25 3037.5,25 3237.5,25 3437.5,25 3637.5,25 3865,25 25,217.5 3865,227 25,417.5 3865,427 25,617.5 3865,627 25,817.5 3865,827 25,1017.5 3865,1027 25,1217.5 3865,1227 3865,1427 25,1432.5 3865,1627 25,1682.5 3865,1827 25,1882.5 3865,2027 25,2082.5 3865,2227 25,2272.5 3865,2427 25,2472.5 3865,2627 25,2672.5 3865,2827 25,2872.5 3865,3027 25,3072.5 3865,3227 25,3272.5 3865,3427 25,3472.5 3865,3627 25,3672.5 25,3865 207.5,3865 397.5,3865 587.5,3865 777.5,3865 967.5,3865 1157.5,3865 1347.5,3865 1537.5,3865 1717.5,3865 1907.5,3865 2097.5,3865 2297.5,3865 2480,3865 2890,3865 3092.5,3865 3292.5,3865 3482.5,3865 3682.5,3865 3865,3865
